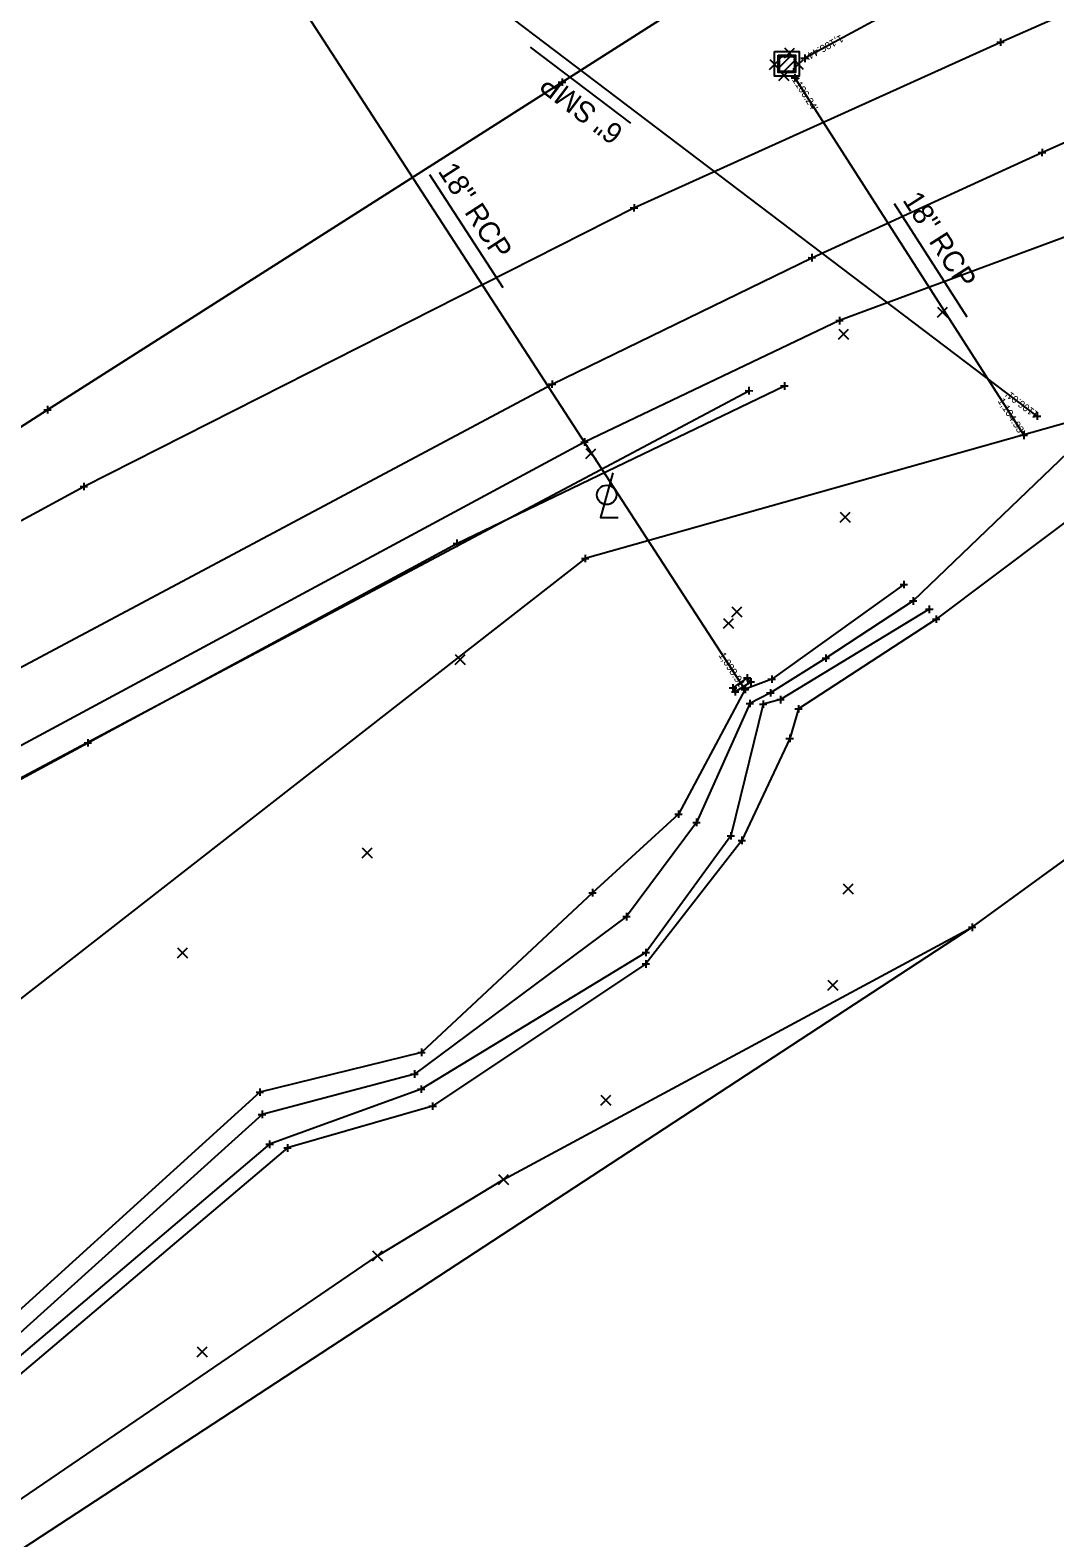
# Model space of a CAD drawing. Extents: x 142461 to 147261, y 511126 to 514697.
# Drawn here: x 144301.4 to 144438.7, y 512563.9 to 512765.9 of the extents above; entities that cross this region are included whole.
import ezdxf

# ---------------------------------------------------------------- set-up
doc = ezdxf.new("R2010")
doc.units = 0
for name, color, linetype in [('DR_X_Cells', 7, 'Continuous'), ('DR_X_Ditch', 7, 'Continuous'), ('DR_X_Elev_Flow', 7, 'Continuous'), ('DR_X_Headwall', 7, 'Continuous'), ('DR_X_Storm_Sewer', 7, 'Continuous'), ('DR_X_Text', 7, 'Continuous'), ('GK_Drainage_Nodes', 7, 'Continuous'), ('LT_X_Poles', 7, 'Continuous'), ('PM_X_Surveyed_Line', 7, 'Continuous'), ('PV_X_EOP', 7, 'Continuous'), ('RD_X_Fence', 7, 'Continuous'), ('RD_X_GR_Rt', 7, 'Continuous'), ('SC_Scratch1', 7, 'Continuous'), ('SV_X_Original_Ground', 7, 'Continuous'), ('SV_X_Random_Point', 7, 'Continuous'), ('SV_X_Shot_Marker', 7, 'Continuous'), ('SV_X_Toe_of_Slope', 7, 'Continuous'), ('SV_X_Top_of_Bank', 7, 'Continuous'), ('VG_X_Tree_Line_Rt', 7, 'Continuous')]:
    doc.layers.add(name, color=color, linetype=linetype)

msp = doc.modelspace()

# ---------------------------------------------------------------- linework, layer by layer
at = {"layer": 'DR_X_Cells'}
for p, q in [((144401.65, 512760.75), (144403.41, 512762.51)), ((144401.65, 512761.88), (144402.28, 512762.51)), ((144402.25, 512760.22), (144403.94, 512761.91)), ((144403.38, 512760.22), (144403.94, 512760.78))]:
    msp.add_line(p, q, dxfattribs=at)
for points in [[(144401.13, 512763.03), (144404.46, 512763.03), (144404.46, 512759.7), (144401.13, 512759.7)], [(144401.65, 512762.51), (144403.94, 512762.51), (144403.94, 512760.22), (144401.65, 512760.22)], [(144401.8, 512762.36), (144403.8, 512762.36), (144403.8, 512760.36), (144401.8, 512760.36)]]:
    msp.add_lwpolyline(points, close=True, dxfattribs=at)
at = {"layer": 'DR_X_Ditch'}
msp.add_lwpolyline([(144511.53, 512751.89), (144440.42, 512709.24), (144419.72, 512689.41), (144408.01, 512681.74), (144400.58, 512677.1), (144397.82, 512675.68), (144390.68, 512659.75), (144381.31, 512647.12), (144352.88, 512626.03), (144332.47, 512620.63), (144289.91, 512582.25), (144265.7, 512565.3), (144238.63, 512545.16), (144206.55, 512520.94), (144168.69, 512495.64), (144160.49, 512489.21), (144140.27, 512478.68)], dxfattribs=at)
at = {"layer": 'DR_X_Elev_Flow'}
for p, q in [((144404.68, 512762.11), (144405.68, 512762.11)), ((144405.18, 512762.61), (144405.18, 512761.61)), ((144405.18, 512762.11), (144405.18, 512762.11)), ((144403.87, 512760), (144403.87, 512759)), ((144403.37, 512759.5), (144404.37, 512759.5)), ((144403.87, 512759.5), (144403.87, 512759.5))]:
    msp.add_line(p, q, dxfattribs=at)
at = {"layer": 'DR_X_Headwall'}
msp.add_lwpolyline([(144395.57, 512677.78), (144395.86, 512677.23), (144397.97, 512678.56), (144397.48, 512679.12)], close=True, dxfattribs=at)
at = {"layer": 'DR_X_Storm_Sewer'}
for p, q in [((144539.42, 512834.67), (144405.18, 512762.11)), ((144436.32, 512714.17), (144319.12, 512803.04)), ((144316.81, 512801.31), (144397.17, 512677.56)), ((144403.87, 512759.5), (144434.53, 512711.6))]:
    msp.add_line(p, q, dxfattribs=at)
at = {"layer": 'DR_X_Text'}
for p, q in [((144368.41, 512763.6), (144381.85, 512753.4)), ((144364.79, 512731.36), (144354.96, 512746.5)), ((144426.96, 512727.43), (144417.23, 512742.63))]:
    msp.add_line(p, q, dxfattribs=at)
at = {"layer": 'GK_Drainage_Nodes'}
for p, q in [((144402.8, 512763.03), (144402.8, 512763.03)), ((144402.8, 512762.36), (144402.8, 512762.36)), ((144401.8, 512761.36), (144401.8, 512761.36)), ((144402.8, 512761.36), (144402.8, 512761.36)), ((144402.8, 512761.36), (144402.8, 512761.36)), ((144402.8, 512761.36), (144402.8, 512761.36)), ((144402.8, 512760.36), (144402.8, 512760.36)), ((144403.8, 512761.36), (144403.8, 512761.36)), ((144402.8, 512759.7), (144402.8, 512759.7))]:
    msp.add_line(p, q, dxfattribs=at)
at = {"layer": 'LT_X_Poles'}
msp.add_lwpolyline([(144379.47, 512706.56), (144377.83, 512700.59), (144380.19, 512700.57)], dxfattribs=at)
msp.add_circle((144378.65, 512703.62), 1.3, dxfattribs=at)
at = {"layer": 'PM_X_Surveyed_Line'}
for points in [[(144079.63, 512572.09), (144161.19, 512623.62), (144232.68, 512669.39), (144303.71, 512715.03), (144372.67, 512758.92), (144417.33, 512787.4), (144522.55, 512854.42), (144628.96, 512922.1), (144693.88, 512963.42), (144795.96, 513028.33), (144851.81, 513063.86), (144912.86, 513102.61), (144997.35, 513156.18), (145071.95, 513203.81), (145158.73, 513259.05)], [(144161.19, 512623.62), (144234.91, 512664.76), (144308.58, 512704.75), (144382.31, 512742.08), (144431.43, 512764.26), (144460.46, 512777.08), (144499.91, 512794.34), (144547.7, 512814.68), (144592.59, 512833.3), (144667.23, 512864.35), (144709.98, 512882.09), (144731.76, 512891.11), (144777.76, 512910.35), (144847.49, 512940.98), (144877.97, 512956.57), (144906.17, 512973.31), (144970.66, 513014.86), (145008.54, 513039.23), (145047.45, 513063.87), (145126.17, 513113.66), (145208.14, 513166.05), (145269.39, 513204.92)], [(144107.76, 512571.5), (144171, 512608.92), (144233.75, 512643.91), (144295.17, 512677.9), (144371.33, 512718.45), (144406.15, 512735.4), (144436.98, 512749.5), (144470.36, 512764.31), (144526.68, 512788.67), (144607.27, 512822.36), (144672.99, 512849.66), (144737.98, 512876.7), (144783.51, 512895.57), (144854.72, 512926.92), (144917.44, 512958.12), (144951.07, 512971.35), (144954.37, 512973.11)]]:
    msp.add_lwpolyline(points, dxfattribs=at)
at = {"layer": 'PV_X_EOP'}
for p, q in [((144441.83, 512738.81), (144409.85, 512726.97)), ((144409.85, 512726.97), (144375.69, 512710.7)), ((144375.69, 512710.7), (144298.52, 512669.16))]:
    msp.add_line(p, q, dxfattribs=at)
at = {"layer": 'RD_X_Fence'}
msp.add_lwpolyline([(143478.94, 512019.34), (143711.38, 512177.16), (144427.62, 512645.69), (144477.47, 512681.98), (144582.58, 512758.57), (144706.18, 512806.24), (144763.41, 512828.73), (144839.36, 512854.89), (144928.89, 512885.13), (144926.13, 512699.9), (144921.71, 512476.45), (144997.12, 512524.34), (145097.9, 512588.02), (145394.3, 512776.52), (145562.04, 512882.95), (145736.06, 512993.23), (145625.27, 513165.45), (145520.47, 513331.41), (145754.83, 513482.5), (146985.53, 514272.72), (147146.04, 514395.19)], dxfattribs=at)
at = {"layer": 'RD_X_GR_Rt'}
msp.add_lwpolyline([(143448.32, 512153.7), (143511.36, 512194.09), (143595.65, 512247.67), (143679.91, 512301.26), (143717.04, 512324.42), (143755.21, 512345.36), (143794.46, 512364.87), (143816.42, 512376.63), (143838.06, 512389.21), (143885.8, 512418.65), (143943.96, 512455.12), (143991.45, 512485.09), (144054.24, 512524.66), (144112.98, 512561.46), (144177.85, 512599.08), (144237.75, 512632.35), (144298.38, 512664.77), (144397.72, 512717.58)], dxfattribs=at)
at = {"layer": 'SV_X_Original_Ground'}
for points in [[(145158.73, 513259.05), (145071.95, 513203.81), (144997.35, 513156.18), (144912.86, 513102.61), (144851.81, 513063.86), (144795.96, 513028.33), (144693.88, 512963.42), (144628.96, 512922.1), (144522.55, 512854.42), (144417.33, 512787.4), (144372.67, 512758.92), (144303.71, 512715.03), (144232.68, 512669.39), (144161.19, 512623.62), (144079.63, 512572.09)], [(144146.46, 512461.37), (144182.31, 512479.61), (144214, 512505.32), (144287, 512560.13), (144347.93, 512601.69), (144364.84, 512611.91), (144427.62, 512645.69), (144477.47, 512681.98), (144514.41, 512743.19), (144582.58, 512758.57), (144622.22, 512785.58), (144706.18, 512806.24)]]:
    msp.add_lwpolyline(points, dxfattribs=at)
at = {"layer": 'SV_X_Random_Point'}
for p, q in [((144400.47, 512760.63), (144401.82, 512761.95)), ((144400.49, 512761.96), (144401.81, 512760.62)), ((144402.46, 512762.17), (144403.8, 512763.49)), ((144402.47, 512763.51), (144403.79, 512762.16)), ((144403.66, 512760.65), (144405.01, 512761.97)), ((144403.67, 512761.99), (144404.99, 512760.64)), ((144401.74, 512759.14), (144403.09, 512760.46)), ((144401.75, 512760.47), (144403.07, 512759.12)), ((144423, 512727.44), (144424.33, 512728.78)), ((144423, 512728.78), (144424.33, 512727.44)), ((144409.73, 512724.48), (144411.07, 512725.81)), ((144409.74, 512725.82), (144411.06, 512724.47)), ((144375.85, 512708.49), (144377.2, 512709.81)), ((144375.86, 512709.82), (144377.18, 512708.47)), ((144409.95, 512699.97), (144411.28, 512701.31)), ((144409.95, 512701.31), (144411.28, 512699.97)), ((144395.44, 512687.28), (144396.77, 512688.61)), ((144395.44, 512688.61), (144396.77, 512687.28)), ((144394.3, 512685.75), (144395.63, 512687.08)), ((144394.3, 512687.08), (144395.63, 512685.75)), ((144358.35, 512680.9), (144359.69, 512682.23)), ((144358.35, 512682.23), (144359.69, 512680.9)), ((144345.88, 512655), (144347.22, 512656.33)), ((144345.88, 512656.33), (144347.22, 512655)), ((144410.33, 512650.17), (144411.66, 512651.5)), ((144410.33, 512651.5), (144411.66, 512650.17)), ((144321.14, 512641.6), (144322.48, 512642.94)), ((144321.14, 512642.94), (144322.48, 512641.6)), ((144408.28, 512637.27), (144409.61, 512638.6)), ((144408.28, 512638.6), (144409.61, 512637.27)), ((144377.86, 512621.86), (144379.19, 512623.19)), ((144377.86, 512623.19), (144379.19, 512621.86)), ((144364.17, 512611.24), (144365.5, 512612.57)), ((144364.17, 512612.57), (144365.5, 512611.24)), ((144347.26, 512601.02), (144348.59, 512602.36)), ((144347.26, 512602.36), (144348.59, 512601.02)), ((144323.78, 512588.13), (144325.12, 512589.47)), ((144323.78, 512589.47), (144325.12, 512588.13))]:
    msp.add_line(p, q, dxfattribs=at)
at = {"layer": 'SV_X_Shot_Marker'}
for p, q in [((144430.93, 512764.27), (144431.93, 512764.26)), ((144431.43, 512764.76), (144431.42, 512763.76)), ((144431.43, 512764.26), (144431.43, 512764.26)), ((144372.17, 512758.92), (144373.17, 512758.91)), ((144372.68, 512759.42), (144372.67, 512758.42)), ((144372.67, 512758.92), (144372.67, 512758.92)), ((144436.99, 512750), (144436.98, 512749)), ((144436.48, 512749.5), (144437.48, 512749.49)), ((144436.98, 512749.5), (144436.98, 512749.5)), ((144381.81, 512742.08), (144382.81, 512742.07)), ((144382.32, 512742.58), (144382.31, 512741.58)), ((144382.31, 512742.08), (144382.31, 512742.08)), ((144406.15, 512735.9), (144406.14, 512734.9)), ((144405.65, 512735.41), (144406.65, 512735.4)), ((144406.15, 512735.4), (144406.15, 512735.4)), ((144409.35, 512726.98), (144410.35, 512726.97)), ((144409.85, 512727.47), (144409.84, 512726.47)), ((144409.85, 512726.97), (144409.85, 512726.97)), ((144370.83, 512718.46), (144371.83, 512718.45)), ((144371.33, 512718.95), (144371.32, 512717.95)), ((144371.33, 512718.45), (144371.33, 512718.45)), ((144397.22, 512717.59), (144398.22, 512717.58)), ((144397.72, 512718.08), (144397.71, 512717.08)), ((144397.72, 512717.58), (144397.72, 512717.58)), ((144401.96, 512718.21), (144402.96, 512718.21)), ((144402.46, 512718.71), (144402.46, 512717.71)), ((144402.46, 512718.21), (144402.46, 512718.21)), ((144303.71, 512715.53), (144303.7, 512714.53)), ((144303.21, 512715.03), (144304.21, 512715.02)), ((144303.71, 512715.03), (144303.71, 512715.03)), ((144435.82, 512714.17), (144436.82, 512714.17)), ((144436.32, 512714.67), (144436.32, 512713.67)), ((144436.32, 512714.17), (144436.32, 512714.17)), ((144434.03, 512711.6), (144435.03, 512711.6)), ((144434.53, 512712.1), (144434.53, 512711.1)), ((144434.53, 512711.6), (144434.53, 512711.6)), ((144375.19, 512710.71), (144376.19, 512710.7)), ((144375.7, 512711.2), (144375.69, 512710.2)), ((144375.69, 512710.7), (144375.69, 512710.7)), ((144308.08, 512704.76), (144309.08, 512704.75)), ((144308.59, 512705.25), (144308.58, 512704.25)), ((144308.58, 512704.75), (144308.58, 512704.75)), ((144358.59, 512697.63), (144358.59, 512696.63)), ((144358.09, 512697.13), (144359.09, 512697.13)), ((144358.59, 512697.13), (144358.59, 512697.13)), ((144375.78, 512695.59), (144375.77, 512694.59)), ((144375.27, 512695.09), (144376.27, 512695.08)), ((144375.77, 512695.09), (144375.77, 512695.09)), ((144417.96, 512691.62), (144418.96, 512691.62)), ((144418.46, 512692.12), (144418.46, 512691.12)), ((144418.46, 512691.62), (144418.46, 512691.62)), ((144419.22, 512689.41), (144420.22, 512689.41)), ((144419.72, 512689.91), (144419.72, 512688.91)), ((144419.72, 512689.41), (144419.72, 512689.41)), ((144421.38, 512688.29), (144422.38, 512688.29)), ((144421.88, 512688.79), (144421.88, 512687.79)), ((144421.88, 512688.29), (144421.88, 512688.29)), ((144422.79, 512687.46), (144422.79, 512686.46)), ((144422.29, 512686.96), (144423.29, 512686.96)), ((144422.79, 512686.96), (144422.79, 512686.96)), ((144407.51, 512681.74), (144408.51, 512681.74)), ((144408.01, 512682.24), (144408.01, 512681.24)), ((144408.01, 512681.74), (144408.01, 512681.74)), ((144396.98, 512679.12), (144397.98, 512679.12)), ((144397.48, 512679.62), (144397.48, 512678.62)), ((144397.48, 512679.12), (144397.48, 512679.12)), ((144397.97, 512679.06), (144397.97, 512678.06)), ((144400.76, 512679.43), (144400.76, 512678.43)), ((144395.07, 512677.78), (144396.07, 512677.78)), ((144395.36, 512677.23), (144396.36, 512677.23)), ((144395.57, 512678.28), (144395.57, 512677.28)), ((144395.57, 512677.78), (144395.57, 512677.78)), ((144395.86, 512677.73), (144395.86, 512676.73)), ((144395.86, 512677.23), (144395.86, 512677.23)), ((144396.67, 512677.56), (144397.67, 512677.56)), ((144396.72, 512677.58), (144397.72, 512677.58)), ((144397.17, 512678.06), (144397.17, 512677.06)), ((144397.17, 512677.56), (144397.17, 512677.56)), ((144397.22, 512678.08), (144397.22, 512677.08)), ((144397.22, 512677.58), (144397.22, 512677.58)), ((144397.47, 512678.56), (144398.47, 512678.56)), ((144397.97, 512678.56), (144397.97, 512678.56)), ((144400.08, 512677.1), (144401.08, 512677.1)), ((144400.26, 512678.93), (144401.26, 512678.93)), ((144400.58, 512677.6), (144400.58, 512676.6)), ((144400.58, 512677.1), (144400.58, 512677.1)), ((144400.76, 512678.93), (144400.76, 512678.93)), ((144397.32, 512675.68), (144398.32, 512675.68)), ((144397.82, 512676.18), (144397.82, 512675.18)), ((144397.82, 512675.68), (144397.82, 512675.68)), ((144399.12, 512675.58), (144400.12, 512675.58)), ((144399.62, 512676.08), (144399.62, 512675.08)), ((144399.62, 512675.58), (144399.62, 512675.58)), ((144401.43, 512676.19), (144402.43, 512676.19)), ((144401.93, 512676.69), (144401.93, 512675.69)), ((144401.93, 512676.19), (144401.93, 512676.19)), ((144404.36, 512675.45), (144404.36, 512674.45)), ((144403.86, 512674.95), (144404.86, 512674.95)), ((144404.36, 512674.95), (144404.36, 512674.95)), ((144402.67, 512671), (144403.67, 512671)), ((144403.17, 512671.5), (144403.17, 512670.5)), ((144403.17, 512671), (144403.17, 512671)), ((144308.63, 512670.4), (144309.63, 512670.4)), ((144309.13, 512670.9), (144309.13, 512669.9)), ((144309.13, 512670.4), (144309.13, 512670.4)), ((144388.27, 512661.34), (144388.27, 512660.34)), ((144387.77, 512660.84), (144388.77, 512660.84)), ((144388.27, 512660.84), (144388.27, 512660.84)), ((144390.18, 512659.75), (144391.18, 512659.75)), ((144390.68, 512660.25), (144390.68, 512659.25)), ((144390.68, 512659.75), (144390.68, 512659.75)), ((144394.78, 512657.94), (144395.78, 512657.94)), ((144395.28, 512658.44), (144395.28, 512657.44)), ((144395.28, 512657.94), (144395.28, 512657.94)), ((144396.25, 512657.34), (144397.25, 512657.34)), ((144396.75, 512657.84), (144396.75, 512656.84)), ((144396.75, 512657.34), (144396.75, 512657.34)), ((144376.75, 512650.83), (144376.75, 512649.83)), ((144376.25, 512650.33), (144377.25, 512650.33)), ((144376.75, 512650.33), (144376.75, 512650.33)), ((144380.81, 512647.12), (144381.81, 512647.12)), ((144381.31, 512647.62), (144381.31, 512646.62)), ((144381.31, 512647.12), (144381.31, 512647.12)), ((144427.12, 512645.7), (144428.12, 512645.69)), ((144427.62, 512646.19), (144427.61, 512645.19)), ((144427.62, 512645.69), (144427.62, 512645.69)), ((144383.9, 512642.82), (144383.9, 512641.82)), ((144383.39, 512640.78), (144384.39, 512640.78)), ((144383.4, 512642.32), (144384.4, 512642.32)), ((144383.89, 512641.28), (144383.89, 512640.28)), ((144383.89, 512640.78), (144383.89, 512640.78)), ((144383.9, 512642.32), (144383.9, 512642.32)), ((144353.34, 512628.94), (144354.34, 512628.94)), ((144353.84, 512629.44), (144353.84, 512628.44)), ((144353.84, 512628.94), (144353.84, 512628.94)), ((144352.38, 512626.03), (144353.38, 512626.03)), ((144352.88, 512626.53), (144352.88, 512625.53)), ((144352.88, 512626.03), (144352.88, 512626.03)), ((144353.8, 512624.51), (144353.8, 512623.51)), ((144331.67, 512623.61), (144332.67, 512623.61)), ((144332.17, 512624.11), (144332.17, 512623.11)), ((144332.17, 512623.61), (144332.17, 512623.61)), ((144353.3, 512624.01), (144354.3, 512624.01)), ((144353.8, 512624.01), (144353.8, 512624.01)), ((144331.97, 512620.63), (144332.97, 512620.63)), ((144332.47, 512621.13), (144332.47, 512620.13)), ((144332.47, 512620.63), (144332.47, 512620.63)), ((144354.83, 512621.72), (144355.83, 512621.72)), ((144355.33, 512622.22), (144355.33, 512621.22)), ((144355.33, 512621.72), (144355.33, 512621.72)), ((144332.99, 512616.62), (144333.99, 512616.62)), ((144333.49, 512617.12), (144333.49, 512616.12)), ((144333.49, 512616.62), (144333.49, 512616.62)), ((144335.88, 512616.63), (144335.88, 512615.63)), ((144335.38, 512616.13), (144336.38, 512616.13)), ((144335.88, 512616.13), (144335.88, 512616.13))]:
    msp.add_line(p, q, dxfattribs=at)
at = {"layer": 'SV_X_Toe_of_Slope'}
for points in [[(144418.46, 512691.62), (144400.76, 512678.93), (144397.22, 512677.58), (144388.27, 512660.84), (144376.75, 512650.33), (144353.84, 512628.94), (144332.17, 512623.61), (144288.12, 512583.69), (144265.98, 512566.75), (144236.24, 512548), (144204.39, 512524.84), (144167.99, 512498.67), (144153.38, 512502.34)], [(144421.88, 512688.29), (144401.93, 512676.19), (144399.62, 512675.58), (144395.28, 512657.94), (144383.9, 512642.32), (144353.8, 512624.01), (144333.49, 512616.62), (144291.3, 512580.93), (144267.1, 512562.49), (144239.19, 512544.26), (144209.12, 512520.01), (144172.34, 512491.51), (144163.15, 512482.63)]]:
    msp.add_lwpolyline(points, dxfattribs=at)
at = {"layer": 'SV_X_Top_of_Bank'}
for points in [[(144733.96, 512831.9), (144682.77, 512811.9), (144622.22, 512785.58), (144559.34, 512760.99), (144514.41, 512743.19), (144445.8, 512704.27), (144422.79, 512686.96), (144404.36, 512674.95), (144403.17, 512671), (144396.75, 512657.34), (144383.89, 512640.78), (144355.33, 512621.72), (144335.88, 512616.13), (144292.97, 512579.83), (144267.67, 512559.63), (144244.44, 512540.09), (144210.27, 512518.05), (144173.39, 512489.57), (144164.15, 512481.04)], [(144156.07, 512586), (144199.43, 512610.69), (144232.3, 512628.73), (144270.54, 512649.61), (144309.13, 512670.4), (144358.59, 512697.13), (144402.46, 512718.21)]]:
    msp.add_lwpolyline(points, dxfattribs=at)
at = {"layer": 'VG_X_Tree_Line_Rt'}
msp.add_lwpolyline([(144921.71, 512476.45), (144926.13, 512699.9), (144928.89, 512885.13), (144828.22, 512889.46), (144750.74, 512847.64), (144698.78, 512825.75), (144584.26, 512777), (144464.04, 512719.97), (144375.77, 512695.09), (143711.38, 512177.16), (143478.94, 512019.34)], dxfattribs=at)

# ---------------------------------------------------------------- texts
at = {"layer": 'DR_X_Text'}
for s, rotation, p in [('6" SMP', 142.8268, (144381.09, 512752.59)), ('18" RCP', 302.9967, (144355.95, 512747)), ('18" RCP', 302.6203, (144418.22, 512743.13))]:
    msp.add_text(s, height=2.8, rotation=rotation, dxfattribs=at).set_placement(p)
at = {"layer": 'SC_Scratch1'}
for s, rotation, p in [("1,106.44'", 208.3903, (144410.03, 512765.3)), ("1106.24'", 302.6203, (144403.45, 512759.24)), ("1106.01'", 142.8268, (144436.63, 512714.57)), ("1,104.93'", 302.6203, (144431, 512716.2)), ("1,098.91'", 302.9967, (144393.6, 512682.13))]:
    msp.add_text(s, height=1, rotation=rotation, dxfattribs=at).set_placement(p)

doc.saveas('drawing.dxf')
